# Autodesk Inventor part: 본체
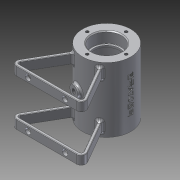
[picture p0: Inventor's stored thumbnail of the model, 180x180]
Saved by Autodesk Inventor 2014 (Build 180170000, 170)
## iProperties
Created: 2016-03
Part Number: 본체
Material: 알루미늄 6061
Document SubType Name: Modeling
Designer: SEC
Density: 2.71 g/cm^3
Appearance: 알루미늄 - 평지
Mass: 211.604 g
Surface Area: 327.768 cm^2
Volume: 78.0825 cm^3
Author: SEC
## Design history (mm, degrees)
sketch "스케치1"
  geometry: C1 r 26 at (0, 0); 1 further point
  constraints: 1 centre point, 1 coincident
  dimensions: "d0" = 52 diameter of C1
extrude "돌출1" new body sketch "스케치1" stored distance "d1" = 70; taper "d2" = 0 deg
sketch "스케치2"
  geometry: C1 r 26 at (0, 0) reference; C2 r 16 at (0, 0)
  constraints: 1 centre point, 1 coincident
  dimensions: "d3" = 32 diameter of C2
extrude "돌출2" cut sketch "스케치2" distance "d4" = 12; taper "d5" = 0 deg
sketch "스케치4"
  geometry: C1 r 16 at (0, 0) reference; C2 r 14 at (0, 0)
  constraints: 1 centre point, 1 coincident
  dimensions: "d9" = 28 diameter of C2
extrude "돌출4" cut sketch "스케치4" distance "d10" = 2; taper "d11" = 0 deg
sketch "스케치5"
  geometry: C1 r 14 at (0, 0) reference; C2 r 21 at (0, 0)
  constraints: 1 centre point, 1 coincident
  dimensions: "d12" = 42 diameter of C2
extrude "돌출5" cut sketch "스케치5" distance "d13" = 42; taper "d14" = 0 deg
sketch "스케치6"
  geometry: C1 r 26 at (0, 0) reference; C2 r 16 at (0, 0)
  constraints: 1 centre point, 1 coincident
  dimensions: "d15" = 32 diameter of C2
extrude "돌출6" cut sketch "스케치6" distance "d16" = 12; taper "d17" = 0 deg
sketch "스케치7"
  geometry: C1 r 16 at (0, 0) reference; C2 r 14 at (0, 0)
  constraints: 1 centre point, 1 coincident
  dimensions: "d18" = 28 diameter of C2
extrude "돌출7" cut sketch "스케치7" distance "d19" = 2; taper "d20" = 0 deg
node "작업 평면1"
sketch "스케치8"
  geometry: C1 r 5 at (0, 0); 1 further point
  constraints: 1 centre point, 1 coincident
  dimensions: "d22" = 10 diameter of C1
extrude "돌출8" join sketch "스케치8" stored distance "d23" = 10 (= d22); taper "d24" = 0 deg
sketch "스케치10"
  geometry: L1 (0, 0)-(21, 0); C1 r 26 at (0, 0) reference; 1 further point
  constraints: 2 end point, 1 coincident, 1 horizontal
  dimensions: "d25" = 21 distance of L1.start L1.end
hole "구멍1" sketch "스케치10" at (21, 0) diameter "d26" = 3.242; stored, may be unused: countersink angle "d30" = 90 deg, drill point angle "d32" = 118 deg; dims "d27" = 8, "d28" = 4, "d29" = 2, "d31" = 10
hole "구멍2" diameter "d38" = 5.188; stored, may be unused: countersink angle "d42" = 90 deg, drill point angle "d44" = 118 deg; dims "d36" = 10, "d37" = 10, "d39" = 8, "d40" = 4, "d41" = 2, "d43" = 30
node "작업 평면3"
  node "작업 평면2"
sketch "스케치12"
  geometry: C1 r 6 at (0, -21); 1 further point
  constraints: 1 centre point, 1 coincident
  dimensions: "d49" = 12 diameter of C1
extrude "돌출9" join sketch "스케치12" stored distance "d50" = 12 (= d49); taper "d51" = 0 deg
hole "구멍3" diameter "d54" = 5.188; stored, may be unused: countersink angle "d58" = 90 deg, drill point angle "d60" = 118 deg; dims "d52" = 10, "d53" = 10, "d55" = 8, "d56" = 4, "d57" = 2, "d59" = 30
node "작업 평면4"
sketch "스케치13"
  geometry: L1 (-15.629, -20.778)-(-36.83, -57.5); L2 (-32.5, -65)-(32.5, -65); L3 (36.83, -57.5)-(15.629, -20.778); L4 (0, 0)-(0, -65); L5 (13.126, -22.443)-(34.232, -59); L6 (32.5, -62)-(-32.5, -62); L7 (-34.232, -59)-(-13.126, -22.443); C1 r 16 at (0, 0) reference; A1 r 26 centre (0, 0) between (-15.629, -20.778) and (15.629, -20.778) reference; A2 r 26 centre (0, 0) between (-15.629, -20.778) and (-13.126, -22.443); A3 r 26 centre (0, 0) between (13.126, -22.443) and (15.629, -20.778); A4 r 5 centre (-32.5, -60) between (-36.83, -57.5) and (-32.5, -65); A5 r 5 centre (32.5, -60) between (32.5, -65) and (36.83, -57.5); A6 r 2 centre (32.5, -60) between (32.5, -62) and (34.232, -59); A7 r 2 centre (-32.5, -60) between (-34.232, -59) and (-32.5, -62); 4 further points
  constraints: 16 point on circle, 14 end point, 6 centre point, 4 point on line, 4 tangent, 2 midpoint, 1 coincident, 1 equal radius, 1 horizontal, 1 perpendicular, 1 vertical alignment, 4 other
  dimensions: "d62" = 65 distance from line of L2 point (0, 0); "d63" = 30 deg angle of L4 L3; "d64" = 30 deg angle of L4 L1; "d70" = 5 radius of A4; "d71" = 65 distance of L2.start L2.end; "d72" = 3 distance between parallel lines of L2 L6
extrude "돌출10" join sketch "스케치13" distance "d68" = 10; taper "d69" = 0 deg
sketch "스케치14"
  geometry: L1 (65, 0)-(65, 10) reference; L2 (0, 0)-(0, 10) reference; C1 r 3 at (12.5, 5); C2 r 3 at (52.5, 5); 3 further points
  constraints: 2 centre point, 2 horizontal alignment, 2 midpoint
  dimensions: "d73" = 6 diameter of C1; "d74" = 6 diameter of C2; "d75" = 20 horizontal distance of C1.centre point (32.5, 30); "d76" = 20 horizontal distance of C2.centre point (32.5, 30)
extrude "돌출11" cut sketch "스케치14" distance "d77" = 10; taper "d78" = 0 deg
node "작업 평면5"
fillet "모깎기1" dims "d80" = 2, "d81" = 0.3, "d82" = 3, "d83" = 0.5
fillet "모깎기2" dims "d84" = 3
chamfer "모따기1" distance "d85" = 1; stored, may be unused: second distance "d86" = 2, angle "d87" = 45 deg
chamfer "모따기2" distance "d88" = 1; stored, may be unused: second distance "d89" = 2, angle "d90" = 45 deg
node "작업 평면7"
sketch "스케치18"
  geometry: 2 further points
  constraints: 1 coincident, 1 other
feature "엠보싱2" sketch "스케치18" dims "d1" = 70, "d95" = 0.5, "d96" = 0
node "솔리드1"
pattern_circular "원형 패턴1" dims angle "d34" = 360 deg
mirror "대칭1"
mirror "대칭2"
mirror "대칭3"
node "작업축2"
other parameters: "d21" = 29, "d47" = 15 deg, "d48" = -29, "d79" = -26, "d94" = 26
